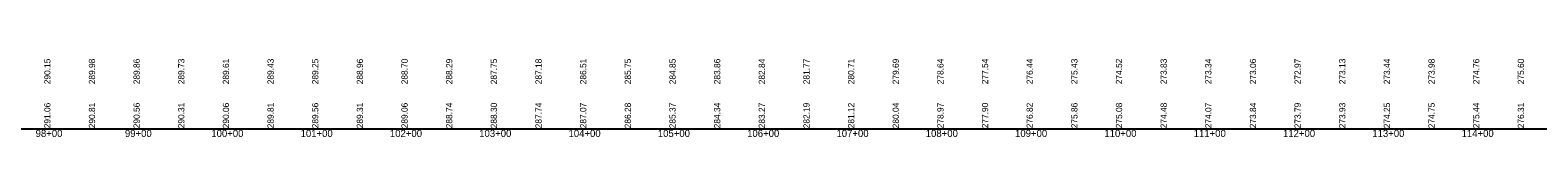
# Model space of a CAD drawing. Extents: x 1876258 to 1932803, y 754739 to 837911.
# Drawn here: x 1888139 to 1889828, y 830495 to 830583 of the extents above; entities that cross this region are included whole.
import ezdxf

# ---------------------------------------------------------------- set-up
doc = ezdxf.new("R2010")
doc.units = 0
for name, color, linetype in [('RD_DDB_StaTX', 7, 'Continuous'), ('RD_DDB_StripGrade', 7, 'Continuous'), ('RD_GPK_Profile_Cell', 7, 'Continuous')]:
    doc.layers.add(name, color=color, linetype=linetype)

msp = doc.modelspace()

# ---------------------------------------------------------------- linework, layer by layer
at = {"layer": 'RD_GPK_Profile_Cell'}
msp.add_line((1878363.1, 830504.3), (1926563.1, 830504.3), dxfattribs=at)

# ---------------------------------------------------------------- texts
at = {"layer": 'RD_DDB_StaTX'}
for s, p in [('98+00', (1888145.5, 830495.3)), ('98+00', (1888145.5, 830495.3)), ('99+00', (1888245.5, 830495.3)), ('99+00', (1888245.5, 830495.3)), ('100+00', (1888342.2, 830495.3)), ('100+00', (1888342.2, 830495.3)), ('101+00', (1888442.2, 830495.3)), ('101+00', (1888442.2, 830495.3)), ('102+00', (1888542.2, 830495.3)), ('102+00', (1888542.2, 830495.3)), ('103+00', (1888642.2, 830495.3)), ('103+00', (1888642.2, 830495.3)), ('104+00', (1888742.2, 830495.3)), ('104+00', (1888742.2, 830495.3)), ('105+00', (1888842.2, 830495.3)), ('105+00', (1888842.2, 830495.3)), ('106+00', (1888942.2, 830495.3)), ('106+00', (1888942.2, 830495.3)), ('107+00', (1889042.2, 830495.3)), ('107+00', (1889042.2, 830495.3)), ('108+00', (1889142.2, 830495.3)), ('108+00', (1889142.2, 830495.3)), ('109+00', (1889242.2, 830495.3)), ('109+00', (1889242.2, 830495.3)), ('110+00', (1889342.2, 830495.3)), ('110+00', (1889342.2, 830495.3)), ('111+00', (1889442.2, 830495.3)), ('111+00', (1889442.2, 830495.3)), ('112+00', (1889542.2, 830495.3)), ('112+00', (1889542.2, 830495.3)), ('113+00', (1889642.2, 830495.3)), ('113+00', (1889642.2, 830495.3)), ('114+00', (1889742.2, 830495.3)), ('114+00', (1889742.2, 830495.3))]:
    msp.add_text(s, height=8, dxfattribs=at).set_placement(p)
at = {"layer": 'RD_DDB_StripGrade'}
for s, p in [('290.15', (1888162.1, 830554.3)), ('289.98', (1888212.1, 830554.3)), ('289.86', (1888262.1, 830554.3)), ('289.73', (1888312.1, 830554.3)), ('289.61', (1888362.1, 830554.3)), ('289.43', (1888412.1, 830554.3)), ('289.25', (1888462.1, 830554.3)), ('288.96', (1888512.1, 830554.3)), ('288.70', (1888562.1, 830554.3)), ('288.29', (1888612.1, 830554.3)), ('287.75', (1888662.1, 830554.3)), ('287.18', (1888712.1, 830554.3)), ('286.51', (1888762.1, 830554.3)), ('285.75', (1888812.1, 830554.3)), ('284.85', (1888862.1, 830554.3)), ('283.86', (1888912.1, 830554.3)), ('282.84', (1888962.1, 830554.3)), ('281.77', (1889012.1, 830554.3)), ('280.71', (1889062.1, 830554.3)), ('279.69', (1889112.1, 830554.3)), ('278.64', (1889162.1, 830554.3)), ('277.54', (1889212.1, 830554.3)), ('276.44', (1889262.1, 830554.3)), ('275.43', (1889312.1, 830554.3)), ('274.52', (1889362.1, 830554.3)), ('273.83', (1889412.1, 830554.3)), ('273.34', (1889462.1, 830554.3)), ('273.06', (1889512.1, 830554.3)), ('272.97', (1889562.1, 830554.3)), ('273.13', (1889612.1, 830554.3)), ('273.44', (1889662.1, 830554.3)), ('273.98', (1889712.1, 830554.3)), ('274.76', (1889762.1, 830554.3)), ('275.60', (1889812.1, 830554.3)), ('291.06', (1888162.1, 830505)), ('290.81', (1888212.1, 830505)), ('290.56', (1888262.1, 830505)), ('290.31', (1888312.1, 830505)), ('290.06', (1888362.1, 830505)), ('289.81', (1888412.1, 830505)), ('289.56', (1888462.1, 830505)), ('289.31', (1888512.1, 830505)), ('289.06', (1888562.1, 830505)), ('288.74', (1888612.1, 830505)), ('288.30', (1888662.1, 830505)), ('287.74', (1888712.1, 830505)), ('287.07', (1888762.1, 830505)), ('286.28', (1888812.1, 830505)), ('285.37', (1888862.1, 830505)), ('284.34', (1888912.1, 830505)), ('283.27', (1888962.1, 830505)), ('282.19', (1889012.1, 830505)), ('281.12', (1889062.1, 830505)), ('280.04', (1889112.1, 830505)), ('278.97', (1889162.1, 830505)), ('277.90', (1889212.1, 830505)), ('276.82', (1889262.1, 830505)), ('275.86', (1889312.1, 830505)), ('275.08', (1889362.1, 830505)), ('274.48', (1889412.1, 830505)), ('274.07', (1889462.1, 830505)), ('273.84', (1889512.1, 830505)), ('273.79', (1889562.1, 830505)), ('273.93', (1889612.1, 830505)), ('274.25', (1889662.1, 830505)), ('274.75', (1889712.1, 830505)), ('275.44', (1889762.1, 830505)), ('276.31', (1889812.1, 830505))]:
    msp.add_text(s, height=7, rotation=90, dxfattribs=at).set_placement(p)

doc.saveas('drawing.dxf')
